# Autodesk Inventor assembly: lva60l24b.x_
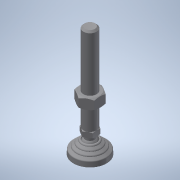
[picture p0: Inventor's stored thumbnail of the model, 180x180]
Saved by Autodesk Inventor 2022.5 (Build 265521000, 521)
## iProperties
Part Number: lva60l24b.x_
Material: 一般
Document SubType Name: Assembly
Designer: ImaoCorp
Sending System: SOLIDWORKS 2017-2017317
MC: AMD64
MC_MODEL: Intel64 Family 6 Model 60 Stepping 3, GenuineIntel
OS: Windows_NT
FRU: Parasolid Version 29.0, build 201,  4-17-2017
FORMAT: text
GUISE: transmit
KEY: lva60l24b
FILE: lva60l24b.x_t
DATE: Mon Jul 01 18:06:19 2019
Author: ImaoCorp
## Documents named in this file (3)
- X:\14_SW2022-Inv2022\00_全2023-1023新製品(TCC)まで\l\lva60l24b\LVA60L24B.iam
- X:\14_SW2022-Inv2022\00_全2023-1023新製品(TCC)まで\l\lva60l24b\lva60l24b_01.ipt
- X:\14_SW2022-Inv2022\00_全2023-1023新製品(TCC)まで\l\lva60l24b\lva60l24b_02.ipt
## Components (2 placed, 2 different names)
1. lva60l24b_01
2. lva60l24b_02
